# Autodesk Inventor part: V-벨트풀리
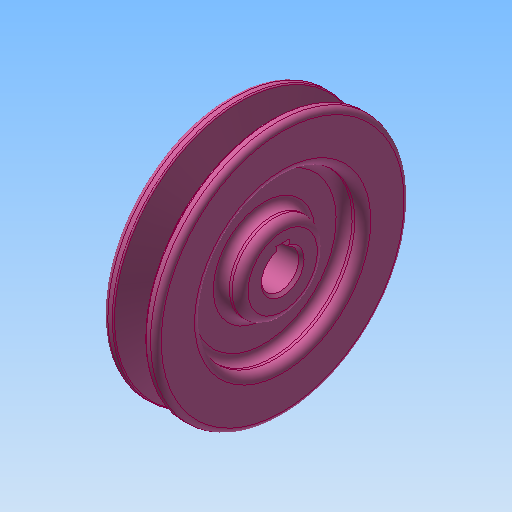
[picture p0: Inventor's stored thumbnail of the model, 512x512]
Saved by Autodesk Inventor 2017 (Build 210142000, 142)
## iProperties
Created: 2020-05
Part Number: V-벨트풀리
Material: 알루미늄 6061
Document SubType Name: Modeling
Designer: mduedu
Density: 1 g/cm^3
Appearance: 분홍색
Author: mduedu
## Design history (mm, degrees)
sketch "스케치1"
  geometry: L1 (-10, 0)-(10, 0); L2 (10, 47.5)-(-10, 47.5); L3 (-5.976, 47.5)-(-2.154, 35); L4 (-2.154, 35)-(2.154, 35); L5 (2.154, 35)-(5.976, 47.5); L6 (0, 0)-(0, 47.5); L7 (-10, 30)-(-3, 30); L8 (-3, 30)-(-3, 16); L9 (-3, 16)-(-10, 16); L10 (-10, 47.5)-(-10, 30); L11 (-10, 16)-(-10, 0); L12 (10, 30)-(3, 30); L13 (3, 30)-(3, 16); L14 (3, 16)-(10, 16); L15 (10, 0)-(10, 16); L16 (10, 30)-(10, 47.5); L17 (-4.6, 43)-(4.6, 43); 2 further points
  constraints: 34 end point, 6 parallel, 6 perpendicular, 4 point on line, 4 symmetric about line, 3 midpoint, 2 horizontal, 1 coincident, 1 collinear, 1 equal length, 1 vertical alignment
  dimensions: "d0" = 95 diameter of L2 L1; "d2" = 20 distance between parallel lines of L16 L10; "d3" = 6 distance between parallel lines of L13 L8; "d4" = 32 diameter of L14 L1; "d5" = 60 diameter of L12 L1; "d6" = 4.5 distance between parallel lines of L17 L2; "d7" = 8 distance between parallel lines of L4 L17; "d8" = 34 deg angle of L5 L3; "d9" = 9.2 distance of L17.start L17.end
revolve "회전1" sketch "스케치1" stored, may be unused: angle "d10" = 90 deg
sketch "스케치2"
  geometry: L1 (-2.5, 6.538)-(2.5, 6.538); L2 (2.5, 6.538)-(2.5, 9.3); L3 (2.5, 9.3)-(-2.5, 9.3); L4 (-2.5, 9.3)-(-2.5, 6.538); A1 r 7 centre (0, 0) between (-2.5, 6.538) and (2.5, 6.538); 1 further point
  constraints: 8 end point, 2 parallel, 2 point on circle, 1 centre point, 1 coincident, 1 horizontal, 1 perpendicular
  dimensions: "d11" = 14 diameter of A1; "d13" = 16.3 dimension on A1 L3; "d14" = 5 distance of L2.end L3.end
extrude "돌출1" cut sketch "스케치2" stored distance "d15" = 10; taper "d16" = 0 deg
chamfer "모따기1" distance "d17" = 1; stored, may be unused: second distance "d18" = 2, angle "d19" = 45 deg
fillet "모깎기1" dims "d20" = 3
fillet "모깎기2" dims "d21" = 2
fillet "모깎기3" dims "d22" = 1
fillet "모깎기4" dims "d23" = 0.5
fillet "모깎기5" dims "d24" = 3
node "솔리드1"
